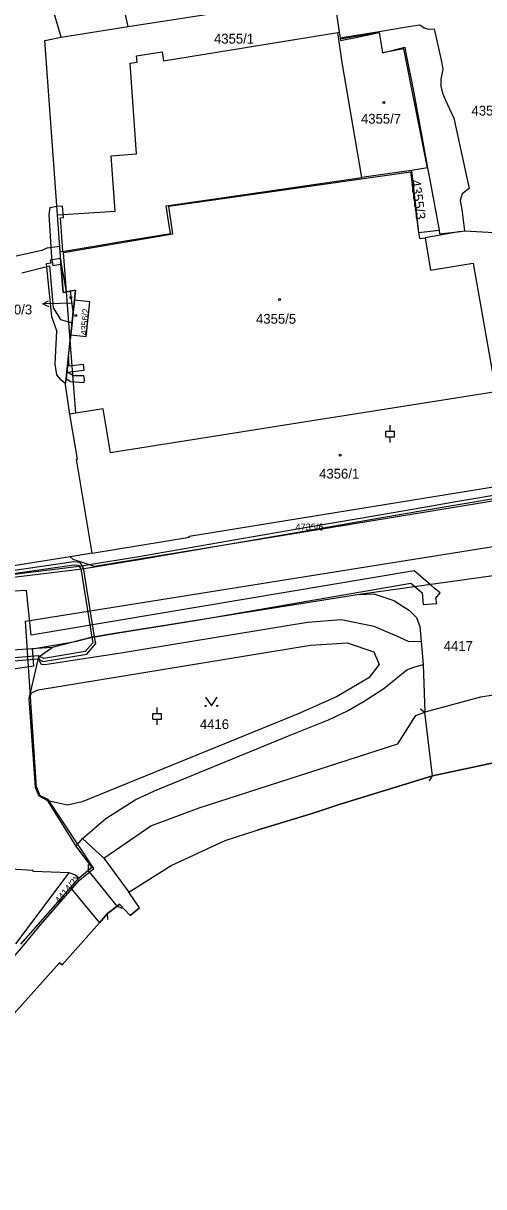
# Model space of a CAD drawing. Extents: x -756746 to -753363, y -1166406 to -1161727.
# Drawn here: x -755989.1 to -755909.2, y -1165835.3 to -1165633.6 of the extents above; entities that cross this region are included whole.
import ezdxf

# ---------------------------------------------------------------- set-up
doc = ezdxf.new("R2010")
doc.units = 0
for name, color, linetype in [('Hranice kat_území', 7, 'Continuous'), ('Hranice parcel', 7, 'Continuous'), ('Parcelní čísla', 7, 'Continuous'), ('Pop  PČ popisy', 7, 'Continuous'), ('Vnitřní kresba', 7, 'Continuous'), ('Věcná břemena k části', 7, 'Continuous'), ('Značky budov', 7, 'Continuous'), ('Značky kultur', 7, 'Continuous')]:
    doc.layers.add(name, color=color, linetype=linetype)

msp = doc.modelspace()

# ---------------------------------------------------------------- linework, layer by layer
at = {"layer": 'Hranice kat_území'}
msp.add_lwpolyline([(-755993.18, -1165808.06), (-755982.75, -1165796.53), (-755982.33, -1165796.88), (-755975.84, -1165789.57), (-755974.43, -1165787.98), (-755972.79, -1165786.68), (-755972.36, -1165786.33), (-755970.52, -1165788.28), (-755968.88, -1165786.97), (-755970.73, -1165784.23), (-755963.38, -1165779.63), (-755954.03, -1165775.31), (-755948.47, -1165773.53), (-755938.75, -1165770.55), (-755934.24, -1165769.07), (-755918.05, -1165764.1), (-755906.71, -1165761.65)], dxfattribs=at)
at = {"layer": 'Hranice parcel'}
for p, q in [((-755918.95, -1165658.67), (-755921.74, -1165659.16)), ((-755980.89, -1165688.57), (-755981.54, -1165680.19)), ((-755980.17, -1165681.65), (-755980.79, -1165687.63)), ((-755980.79, -1165687.63), (-755980.89, -1165688.57)), ((-755980.9, -1165726.12), (-755991.11, -1165727.76)), ((-755977.09, -1165725.5), (-755980.9, -1165726.12)), ((-755980.38, -1165726.62), (-755980.9, -1165726.12)), ((-755901.93, -1165728.65), (-755930.75, -1165732.63)), ((-755977.35, -1165740.09), (-755984.06, -1165741.82)), ((-755984.06, -1165741.82), (-755999.01, -1165742.9)), ((-755906.71, -1165761.65), (-755918.05, -1165764.1)), ((-755990.35, -1165793.23), (-755981.09, -1165780.91))]:
    msp.add_line(p, q, dxfattribs=at)
for points in [[(-755982.49, -1165636.03), (-755985.44, -1165625.87), (-755986.54, -1165622.42), (-755987.71, -1165618.22), (-755996.74, -1165593.66)], [(-755982.49, -1165636.03), (-755970.84, -1165634.21), (-755940.51, -1165629.46), (-755935.31, -1165628.65)], [(-755935.31, -1165628.65), (-755935.2, -1165628.84), (-755934.24, -1165635.19)], [(-755982.66, -1165673.23), (-755983.12, -1165666.86), (-755985.3, -1165636.64), (-755982.49, -1165636.03)], [(-755930.33, -1165660.4), (-755933.73, -1165640.43), (-755934.49, -1165635.23), (-755934.24, -1165635.19)], [(-755934.24, -1165635.19), (-755934.1, -1165636.19), (-755934.07, -1165636.41), (-755934.03, -1165636.63), (-755931.39, -1165636.12), (-755927.33, -1165635.22), (-755927.03, -1165636.98), (-755926.72, -1165638.77), (-755922.89, -1165637.78), (-755922.74, -1165638.51), (-755921.32, -1165645.72), (-755918.95, -1165658.67)], [(-755918.95, -1165658.67), (-755918.62, -1165660.47), (-755916.92, -1165669.49)], [(-755982.66, -1165673.23), (-755976.41, -1165672.2), (-755972.39, -1165671.54), (-755963.49, -1165670.08), (-755963.84, -1165667.94), (-755964.27, -1165665.28), (-755951.43, -1165663.43), (-755930.33, -1165660.4)], [(-755921.74, -1165659.16), (-755925.86, -1165659.75), (-755930.33, -1165660.4)], [(-755921.74, -1165659.16), (-755920.48, -1165669.91), (-755916.92, -1165669.49)], [(-755913.22, -1165669.71), (-755912.53, -1165669.61), (-755907.38, -1165669.9), (-755895.75, -1165667.18)], [(-755913.22, -1165669.71), (-755919.33, -1165670.81), (-755918.45, -1165676.43), (-755913.19, -1165675.58), (-755911.02, -1165675.23), (-755910.72, -1165676.92), (-755907.09, -1165697.52), (-755934.14, -1165701.81), (-755936.4, -1165702.16), (-755959.68, -1165705.85), (-755961.91, -1165706.21), (-755971.03, -1165707.65), (-755972.55, -1165707.89), (-755973.91, -1165708.11), (-755975.19, -1165700.5), (-755979.91, -1165701.21), (-755981, -1165701.37)], [(-755916.92, -1165669.49), (-755916.84, -1165670.12), (-755913.22, -1165669.71)], [(-755981.54, -1165680.19), (-755982.15, -1165680.31), (-755982.54, -1165674.93), (-755982.66, -1165673.23)], [(-755981.54, -1165680.19), (-755979.98, -1165679.9), (-755980.17, -1165681.65)], [(-755980.79, -1165687.63), (-755978.13, -1165687.91), (-755977.53, -1165681.93), (-755980.17, -1165681.65)], [(-755981, -1165701.37), (-755981.71, -1165696.34), (-755980.89, -1165688.57)], [(-755977.09, -1165725.5), (-755979.83, -1165709.2), (-755979.67, -1165709.17), (-755981, -1165701.37)], [(-755977.09, -1165725.5), (-755960.24, -1165722.72), (-755960.26, -1165722.56), (-755905.02, -1165713.59), (-755905, -1165713.76), (-755889.67, -1165711.27), (-755888.15, -1165711.02)], [(-755887.88, -1165713.26), (-755976.69, -1165727.8), (-755980.38, -1165726.62)], [(-755930.75, -1165732.63), (-755972.86, -1165739.35), (-755977.35, -1165740.09)], [(-755930.75, -1165732.63), (-755928.26, -1165732.55), (-755924.81, -1165733.72), (-755922.09, -1165735.46), (-755920.86, -1165736.65), (-755920.3, -1165738.18), (-755920.03, -1165740.83), (-755919.69, -1165744.82), (-755919.43, -1165753.08)], [(-755988.03, -1165750.66), (-755986.35, -1165743.46), (-755984.06, -1165741.82)], [(-755979.88, -1165776.27), (-755984.81, -1165768.42), (-755986.29, -1165767.64), (-755986.94, -1165766.11), (-755988.03, -1165750.66)], [(-755919.43, -1165753.08), (-755919.09, -1165752.96), (-755909.69, -1165750.37), (-755907.58, -1165750.07)], [(-755979.88, -1165776.27), (-755978.76, -1165774.93), (-755975.06, -1165778.37), (-755966.93, -1165772.78), (-755958.56, -1165769.62), (-755924.09, -1165758.57), (-755920.94, -1165753.61), (-755919.43, -1165753.08)], [(-755918.05, -1165764.1), (-755934.24, -1165769.07), (-755938.75, -1165770.55), (-755948.47, -1165773.53)], [(-755968.88, -1165786.97), (-755970.73, -1165784.23), (-755963.38, -1165779.63), (-755954.03, -1165775.31), (-755948.47, -1165773.53)], [(-755979.39, -1165781.84), (-755977.79, -1165780.47), (-755977.17, -1165779.94), (-755979.88, -1165776.27)], [(-755981.09, -1165780.91), (-755987.34, -1165780.65), (-755987.33, -1165780.5), (-755992.3, -1165780.2), (-755992.31, -1165780.35), (-755998.66, -1165779.98), (-756000.66, -1165779.87), (-756000.96, -1165779.85), (-756000.98, -1165780.18), (-756003.5, -1165780.1)], [(-755979.39, -1165781.84), (-755980.08, -1165781.27), (-755981.09, -1165780.91)], [(-755989.46, -1165793.29), (-755980.84, -1165783.49), (-755979.39, -1165781.84)], [(-755968.88, -1165786.97), (-755970.52, -1165788.28), (-755972.36, -1165786.33), (-755972.79, -1165786.68), (-755974.43, -1165787.98), (-755975.84, -1165789.57), (-755982.33, -1165796.88)], [(-755982.33, -1165796.88), (-755982.75, -1165796.53), (-755993.18, -1165808.06), (-755995.65, -1165810.79), (-755996.25, -1165811.45), (-756004.1, -1165821.2), (-756012.95, -1165832.27), (-756014.73, -1165835.32)]]:
    msp.add_lwpolyline(points, dxfattribs=at)
at = {"layer": 'Pop  PČ popisy'}
for p, q in [((-755985.64, -1165682.29), (-755984.66, -1165681.76)), ((-755982.64, -1165682.19), (-755985.64, -1165682.29)), ((-755985.64, -1165682.29), (-755984.62, -1165682.76)), ((-755980.75, -1165682.14), (-755982.64, -1165682.19))]:
    msp.add_line(p, q, dxfattribs=at)
at = {"layer": 'Vnitřní kresba'}
for p, q in [((-755970.84, -1165634.21), (-755973.15, -1165624.03)), ((-755927.34, -1165635.06), (-755922.92, -1165634.33)), ((-755922.92, -1165634.33), (-755920.28, -1165633.9)), ((-755920.28, -1165633.9), (-755919.51, -1165634.4)), ((-755919.51, -1165634.4), (-755918.79, -1165634.64)), ((-755964.71, -1165640.13), (-755934.49, -1165635.23)), ((-755934.1, -1165636.19), (-755927.34, -1165635.06)), ((-755927.33, -1165635.22), (-755934.07, -1165636.41)), ((-755918.79, -1165634.64), (-755917.76, -1165634.61)), ((-755917.76, -1165634.61), (-755916.59, -1165640.01)), ((-755923.05, -1165638.05), (-755926.72, -1165638.77)), ((-755918.95, -1165658.67), (-755923.05, -1165638.05)), ((-755970.52, -1165640.54), (-755969.29, -1165640.37)), ((-755969.42, -1165656.28), (-755970.52, -1165640.54)), ((-755969.42, -1165639.3), (-755964.97, -1165638.59)), ((-755969.29, -1165640.37), (-755969.42, -1165639.3)), ((-755964.97, -1165638.59), (-755964.71, -1165640.13)), ((-755916.59, -1165640.01), (-755916.29, -1165641.57)), ((-755916.29, -1165641.57), (-755916.65, -1165643.34)), ((-755916.65, -1165643.34), (-755916.62, -1165644.56)), ((-755916.62, -1165644.56), (-755916.37, -1165645.76)), ((-755916.37, -1165645.76), (-755915.88, -1165646.87)), ((-755915.88, -1165646.87), (-755914.39, -1165650.07)), ((-755914.39, -1165650.07), (-755911.73, -1165662.3)), ((-755973.81, -1165656.64), (-755969.42, -1165656.28)), ((-755973.13, -1165666.2), (-755973.81, -1165656.64)), ((-755963.8, -1165665.36), (-755921.9, -1165659.39)), ((-755921.9, -1165659.39), (-755920.48, -1165669.91)), ((-755911.73, -1165662.3), (-755912.93, -1165663.21)), ((-755912.93, -1165663.21), (-755913.27, -1165664.34)), ((-755913.27, -1165664.34), (-755912.98, -1165665.9)), ((-755983.12, -1165666.86), (-755973.13, -1165666.2)), ((-755963.11, -1165670.16), (-755963.8, -1165665.36)), ((-755912.98, -1165665.9), (-755912.53, -1165669.61)), ((-755982.06, -1165673.38), (-755963.11, -1165670.16)), ((-755920.48, -1165669.91), (-755920.34, -1165670.96)), ((-755920.34, -1165670.96), (-755919.33, -1165670.81)), ((-755981.54, -1165680.19), (-755982.06, -1165673.38)), ((-755979.91, -1165701.21), (-755980.89, -1165688.57)), ((-755933.92, -1165737.06), (-755939.78, -1165737.52)), ((-755928.18, -1165738.21), (-755933.92, -1165737.06)), ((-755939.78, -1165737.52), (-755972.45, -1165742.88)), ((-755923.76, -1165740.13), (-755928.18, -1165738.21)), ((-755939.22, -1165741.43), (-755932.89, -1165741.04)), ((-755932.89, -1165741.04), (-755928.24, -1165742.6)), ((-755922.15, -1165740.87), (-755923.76, -1165740.13)), ((-755920.03, -1165740.83), (-755922.15, -1165740.87)), ((-755986.44, -1165749.2), (-755939.22, -1165741.43)), ((-755972.45, -1165742.88), (-755977.8, -1165743.69)), ((-755928.24, -1165742.6), (-755927.34, -1165744.82)), ((-755986.19, -1165744.26), (-755986.35, -1165743.46)), ((-755985.89, -1165744.79), (-755986.19, -1165744.26)), ((-755985.31, -1165744.85), (-755985.89, -1165744.79)), ((-755977.8, -1165743.69), (-755985.31, -1165744.85)), ((-755927.34, -1165744.82), (-755929.13, -1165747.11)), ((-755922.53, -1165745.72), (-755921.49, -1165745.33)), ((-755921.49, -1165745.33), (-755919.69, -1165744.82)), ((-755929.13, -1165747.11), (-755934.73, -1165750.42)), ((-755926.53, -1165748.94), (-755922.53, -1165745.72)), ((-755987.64, -1165749.73), (-755986.44, -1165749.2)), ((-755929.95, -1165751.16), (-755926.53, -1165748.94)), ((-755988.03, -1165750.66), (-755987.64, -1165749.73)), ((-755934.73, -1165750.42), (-755941.39, -1165753.37)), ((-755932.81, -1165752.8), (-755929.95, -1165751.16)), ((-755941.39, -1165753.37), (-755978.83, -1165768.62)), ((-755936.11, -1165754.39), (-755932.81, -1165752.8)), ((-755920.23, -1165752.48), (-755919.43, -1165753.08)), ((-755918.05, -1165764.1), (-755919.43, -1165753.08)), ((-755942.76, -1165757.04), (-755936.11, -1165754.39)), ((-755966.29, -1165766.68), (-755942.76, -1165757.04)), ((-755918.59, -1165764.94), (-755918.05, -1165764.1)), ((-755969.63, -1165768.23), (-755966.29, -1165766.68)), ((-755981.38, -1165769.2), (-755984.81, -1165768.42)), ((-755978.83, -1165768.62), (-755981.38, -1165769.2)), ((-755974.71, -1165771.49), (-755969.63, -1165768.23)), ((-755978.76, -1165774.93), (-755974.71, -1165771.49)), ((-755977.79, -1165779.47), (-755977.79, -1165780.47)), ((-755975.06, -1165778.37), (-755970.73, -1165784.23)), ((-755980.38, -1165781.72), (-755979.39, -1165781.84)), ((-755972.79, -1165786.68), (-755977.79, -1165780.47)), ((-755980.84, -1165783.49), (-755975.84, -1165789.57)), ((-755971.88, -1165787.09), (-755972.79, -1165786.68)), ((-755974.36, -1165788.98), (-755974.43, -1165787.98))]:
    msp.add_line(p, q, dxfattribs=at)
for points in [[(-755986.09, -1165767.54), (-755986.77, -1165766.07), (-755988.64, -1165737.29), (-755841.65, -1165713.82)], [(-756011.55, -1165819.67), (-755988.93, -1165793.42), (-755986.05, -1165789.91), (-755979.3, -1165782.2), (-755976.81, -1165780.14), (-755984.75, -1165768.21), (-755986.09, -1165767.54), (-755986.67, -1165766.11)]]:
    msp.add_lwpolyline(points, dxfattribs=at)
at = {"layer": 'Věcná břemena k části'}
for points in [[(-755982.66, -1165673.23), (-755982.21, -1165673.16), (-755982.58, -1165667.37), (-755982.08, -1165667.33), (-755982.22, -1165665.33), (-755983.23, -1165665.4), (-755984.45, -1165665.64), (-755984.6, -1165666.81), (-755984.14, -1165674.29), (-755983.94, -1165675.61), (-755982.51, -1165675.4), (-755982.54, -1165674.93)], [(-755980.79, -1165687.63), (-755980.38, -1165683.63), (-755980.87, -1165680.07), (-755981.54, -1165680.19), (-755982.15, -1165680.31), (-755982.51, -1165675.4), (-755982.54, -1165674.93), (-755982.58, -1165674.42), (-755984.37, -1165674.68), (-755984.29, -1165675.23), (-755985.07, -1165675.31), (-755984.16, -1165684.45), (-755983.26, -1165686.92), (-755983.6, -1165692.75), (-755983.3, -1165694.58), (-755982.65, -1165695.35), (-755981.68, -1165696.06), (-755981.59, -1165695.2), (-755981.37, -1165693.13), (-755981.32, -1165692.64), (-755981.19, -1165691.38)], [(-755981.54, -1165680.19), (-755982.58, -1165674.42), (-755982.54, -1165674.93), (-755982.51, -1165675.4), (-755982.15, -1165680.31)], [(-755981.19, -1165691.38), (-755981.32, -1165692.64), (-755981.37, -1165693.13), (-755981.59, -1165695.2), (-755980.86, -1165695.74), (-755978.48, -1165695.89), (-755978.45, -1165695.39), (-755978.53, -1165694.75), (-755980.32, -1165694.75), (-755981.36, -1165694.11), (-755978.47, -1165693.79), (-755978.58, -1165692.8), (-755981.07, -1165693.07)]]:
    msp.add_lwpolyline(points, close=True, dxfattribs=at)
for points in [[(-755989.29, -1165676.91), (-755984.52, -1165675.66), (-755983.87, -1165682.99), (-755982.62, -1165684.99), (-755980.57, -1165685.54), (-755980.17, -1165681.65), (-755979.98, -1165679.9), (-755982.15, -1165680.31), (-755982.54, -1165674.93), (-755982.66, -1165673.23), (-755982.72, -1165672.34), (-755984.94, -1165672.64), (-755985.84, -1165673.04), (-755990.26, -1165674.03)], [(-755905.07, -1165715.09), (-755914.05, -1165716.62), (-755918.53, -1165717.38)], [(-755993.21, -1165729.93), (-755978.86, -1165728.22), (-755968.95, -1165726.61), (-755960.83, -1165725.2), (-755952.46, -1165723.76), (-755938.38, -1165721.33), (-755927.83, -1165719.5), (-755918.45, -1165717.88), (-755913.97, -1165717.12), (-755904.99, -1165715.59)], [(-755918.53, -1165717.38), (-755927.91, -1165719), (-755938.46, -1165720.83), (-755952.54, -1165723.26), (-755969.03, -1165726.11), (-755977.6, -1165727.51), (-755978.92, -1165727.72), (-755993.51, -1165729.51)], [(-755998.18, -1165744.78), (-755986.44, -1165743.83), (-755985.58, -1165744.25), (-755978.03, -1165743.01), (-755976.48, -1165741.16), (-755976.67, -1165739.98), (-755978.58, -1165728.03), (-755979.2, -1165727.12), (-755980.3, -1165727.02), (-755991.37, -1165728.62)], [(-755991.21, -1165729.1), (-755980.29, -1165727.52), (-755979.48, -1165727.59), (-755979.06, -1165728.22), (-755977.16, -1165740.06), (-755977.01, -1165741.01), (-755978.29, -1165742.55), (-755985.51, -1165743.73), (-755986.25, -1165743.39), (-755986.43, -1165743.3), (-755998.39, -1165744.3)], [(-755997.43, -1165746.48), (-755987.22, -1165745), (-755987.46, -1165742.07), (-755980.05, -1165740.79), (-755977.35, -1165740.09), (-755972.86, -1165739.35), (-755958.87, -1165737.12), (-755921.86, -1165730.71), (-755921.14, -1165731.3), (-755919.88, -1165732.36), (-755919.72, -1165734.39), (-755917.35, -1165734.2), (-755917.48, -1165733.3), (-755916.75, -1165732.36), (-755917.78, -1165731.55), (-755918.47, -1165730.93), (-755921.28, -1165728.58), (-755987.69, -1165739.68), (-755988.51, -1165731.99), (-755990.82, -1165732.09)]]:
    msp.add_lwpolyline(points, dxfattribs=at)
at = {"layer": 'Značky budov'}
for centre in [(-755926.5, -1165647.36), (-755980.78, -1165681.15), (-755944.61, -1165681.53), (-755979.95, -1165684.3), (-755934.07, -1165708.49)]:
    msp.add_circle(centre, 0.175, dxfattribs=at)
at = {"layer": 'Značky kultur'}
for p, q in [((-755926.15, -1165704.33), (-755924.65, -1165704.33)), ((-755926.15, -1165705.33), (-755926.15, -1165704.33)), ((-755925.4, -1165704.33), (-755925.4, -1165703.33)), ((-755924.65, -1165705.33), (-755924.65, -1165704.33)), ((-755926.15, -1165705.33), (-755924.65, -1165705.33)), ((-755925.4, -1165706.33), (-755925.4, -1165705.33)), ((-755966.58, -1165753.27), (-755965.08, -1165753.27)), ((-755966.58, -1165754.27), (-755966.58, -1165753.27)), ((-755965.83, -1165753.27), (-755965.83, -1165752.27)), ((-755965.08, -1165754.27), (-755965.08, -1165753.27)), ((-755966.58, -1165754.27), (-755965.08, -1165754.27)), ((-755965.83, -1165755.27), (-755965.83, -1165754.27))]:
    msp.add_line(p, q, dxfattribs=at)
msp.add_lwpolyline([(-755957.43, -1165750.48), (-755956.43, -1165751.98), (-755955.43, -1165750.48)], dxfattribs=at)
for centre in [(-755957.43, -1165751.98), (-755955.43, -1165751.98)]:
    msp.add_circle(centre, 0.1, dxfattribs=at)

# ---------------------------------------------------------------- texts
at = {"layer": 'Parcelní čísla'}
for s, height, p in [('4355/1', 1.7, (-755955.97, -1165637.16)), ('4354/1', 1.7, (-755911.31, -1165649.63)), ('4355/7', 1.7, (-755930.48, -1165651.04)), ('3960/3', 1.7, (-755994.46, -1165684.11)), ('4355/5', 1.7, (-755948.68, -1165685.72)), ('4356/1', 1.7, (-755937.74, -1165712.57)), ('4735/6', 1.2, (-755941.86, -1165721.56)), ('4417', 1.7, (-755916.14, -1165742.44)), ('4416', 1.7, (-755958.42, -1165755.99))]:
    msp.add_text(s, height=height, dxfattribs=at).set_placement(p)
for s, height, rotation, p in [('4355/3', 1.7, 278, (-755921.88, -1165660.86)), ('4356/2', 1.139, 86, (-755977.96, -1165687.75)), ('4414/2', 1.2, 50, (-755982.77, -1165786.33))]:
    msp.add_text(s, height=height, rotation=rotation, dxfattribs=at).set_placement(p)

doc.saveas('drawing.dxf')
